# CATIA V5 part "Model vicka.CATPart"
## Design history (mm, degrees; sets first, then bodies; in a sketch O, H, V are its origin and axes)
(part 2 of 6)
  Sketch25 on zx-plane, origin (0, 0, 0), H (-1, 0, 0), V (0, 0, 1)
  Sketch26 on face of Pad13, origin (-3.8, 0, 0), H (0, -1, 0), V (0, 0, 1)
    projected line E1 (-60.7671, -19.7) -> (-56.1616, -20.7) from edge [face of Pad12 from Sketch20.L2 | face of Pad13]
    projected arc E2 centre (-32.0438, -10.8008) radius 26.0704 from (-57.6263, -15.8203) to (-56.1616, -20.7) ccw from edge [face of Pad12 | face of Pad13]
    projected arc E3 centre (-71.4411, -6.5318) radius 16.0003 from (-57.2443, -13.9114) to (-55.7471, -3.4163) ccw from edge [face of Pad12 | face of Pad13]
    projected arc E4 centre (-54.1383, -15.5258) radius 3.5004 from (-57.2443, -13.9114) to (-57.6263, -15.8203) ccw from edge [face of Pad12 | face of Pad13]
    projected arc E5 centre (-44.449, -1.1758) radius 11.5181 from (-55.9594, -0.7538) to (-55.7471, -3.4163) ccw from edge [face of Pad12 | face of Pad13]
    projected arc E6 centre (26.1964, -18.2876) radius 84.006 from (-32.7852, 41.5302) to (-55.9594, -0.7538) ccw from edge [face of Pad12 | face of Pad13]
    point P11 (-32.7852, 41.5302)
    projected arc E7 centre (-40.4358, 56.1497) radius 16.5003 from (-32.7852, 41.5302) to (-26.8741, 46.7508) ccw from edge [face of Pad12 from Sketch20.E38 | face of Pad13]
    projected arc E8 centre (-40.4358, 56.1497) radius 16.5003 from (-32.7852, 41.5302) to (-29.3749, 43.9056) ccw from edge [face of Pad12 from Sketch20.E38 | face of Pad13]
    point P13 (-32.7852, 41.5302)
    projected arc E9 centre (-40.437, 56.1511) radius 12.4808 from (-35.0969, 44.8704) to (-32.0107, 46.9441) ccw from edge [face of Rib1 | face of Chamfer2]
    projected arc E10 centre (-40.437, 56.1511) radius 12.4808 from (-35.0969, 44.8704) to (-32.3966, 46.6053) ccw from edge [face of Rib1 | face of Chamfer2]
    point P15 (-35.0969, 44.8704)
    projected line E11 (-35.1853, 44.8093) -> (-35.0969, 44.8704) from edge [face of Pad13 | face of Rib1]
    point P18 (-35.0969, 44.8704)
    projected arc E12 centre (26.197, -18.2879) radius 88.0287 from (-35.1853, 44.8093) to (-59.9554, -0.2097) ccw from edge [face of Rib1 | face of Pad13]
    projected line E13 (-59.963, -0.2667) -> (-59.9554, -0.2097) from edge [face of Pad13 | face of Rib1]
    projected arc E14 centre (-44.4489, -1.1757) radius 15.5408 from (-59.963, -0.2667) to (-59.7178, -4.0697) ccw from edge [face of Rib1 | face of Pad13]
    projected arc E15 centre (-71.4436, -6.5314) radius 11.9814 from (-60.7518, -11.9389) to (-59.7178, -4.0696) ccw from edge [face of Pad13 | face of Rib1]
    projected arc E16 centre (-54.1355, -15.5263) radius 7.5263 from (-60.7518, -11.9388) to (-61.5988, -16.4981) ccw from edge [face of Rib1 | face of Pad13]
    projected line E17 (-61.6023, -16.5212) -> (-61.5988, -16.4981) from edge [face of Pad13 | face of Rib1]
    point P29 (-61.6023, -16.5212)
    projected arc E18 centre (-32.0417, -10.7998) radius 30.1092 from (-61.6023, -16.5212) to (-59.1468, -23.9102) ccw from edge [face of Rib1 | face of Pad13]
    projected arc E19 centre (-32.0417, -10.7998) radius 30.1092 from (-61.6023, -16.5212) to (-60.8054, -19.7) ccw from edge [face of Rib1 | face of Pad13]
    point P31 (-61.6023, -16.5212)
    line L1 (-60.7671, -19.7) -> (-60.8054, -19.7)
    point P33 (-60.8054, -19.7)
    line L2 (-32.3966, 46.6053) -> (-29.3749, 43.9056)
    point P34 (-32.3966, 46.6053)
    point P35 (-29.3749, 43.9056)
    reference projected line E20 (-32.0107, 46.9441) -> (-33.0713, 47.7021) from edge [face of Fillet8 | face of Chamfer2]
    length L2 = 4.052
    distance P34 E20 = 0.5
    coincidence: P33 E18, P34 E9, P35 E7, P11 P13, P15 P18, P29 P31
    horizontal: L1 H
  Pad14: profile Sketch26, direction (-1, 0, 0), length 3.5
  Chamfer3: length 3.5, angle 27, on edge [face of Pad14 | end face of Pad14] (x6)
  Chamfer4: length 3.5, angle 46.25, on edge [face of Pad14 from Sketch26.L2 | end face of Pad14]
  Draft1: Angle 20, Neutral end face of Pad14, PullDir end face of Pad14, SupportToDraft face of Pad14, deactivated
  Draft2: Angle 19, Neutral end face of Pad14, PullDir end face of Pad14, SupportToDraft face of Pad14
  Chamfer5: length 0.044, angle 21, on edge [face of Pad14 | end face of Pocket8]
  Draft3: Angle 20, Neutral end face of Pad14, PullDir end face of Pad14, SupportToDraft face of Pad14, deactivated
  Chamfer6: length 3, second length 1.8, on edge [end face of Pocket8 | face of Pad14] (x6)
  Sketch27 on end face of Pocket8, origin (-0.8, 0, 0), H (0, -1, 0), V (0, 0, 1)
    projected arc E1 centre (26.1964, -18.2876) radius 82.206 from (-31.7063, 40.0656) to (-54.1649, -0.9706) ccw from edge [face of Chamfer6 | end face of Pocket8]
    projected arc E2 centre (26.1964, -18.2876) radius 82.206 from (-50.6914, 10.8) to (-54.1649, -0.9706) ccw from edge [face of Chamfer6 | end face of Pocket8]
    point P2 (-54.1649, -0.9706)
    projected arc E3 centre (-44.449, -1.1758) radius 9.7181 from (-54.1649, -0.9706) to (-53.9815, -3.0662) ccw from edge [face of Chamfer6 | end face of Pocket8]
    point P3 (-54.1649, -0.9706)
    projected arc E4 centre (-71.4411, -6.5318) radius 17.8003 from (-55.6471, -14.7416) to (-53.9815, -3.0658) ccw from edge [face of Chamfer6 | end face of Pocket8]
    projected arc E5 centre (-32.0438, -10.8008) radius 24.2704 from (-55.8377, -15.5862) to (-52.541, -23.7975) ccw from edge [face of Chamfer6 | end face of Pocket8]
    projected arc E6 centre (-54.1383, -15.5258) radius 1.7004 from (-55.6471, -14.7415) to (-55.8377, -15.5862) ccw from edge [face of Chamfer6 | end face of Pocket8]
    projected line E7 (-52.541, -23.7975) -> (-59.867, -22.2068) from edge [face of Chamfer5 | end face of Pocket8]
    projected arc E8 centre (-32.0451, -10.8014) radius 30.0689 from (-59.867, -22.2068) to (-55.0696, -30.1408) ccw from edge [face of Pad11 | end face of Pocket8]
    projected line E9 (-55.0696, -30.1408) -> (-41.0575, -46.8228) from edge [face of Pad11 | end face of Pocket8]
    projected arc E10 centre (-32.4622, -37.7466) radius 12.5004 from (-41.0575, -46.8228) to (-32.5168, -50.2468) ccw from edge [face of Pad11 | end face of Pocket8]
    projected line E11 (-32.5168, -50.2468) -> (-19.8409, -42.7) from edge [face of Pad11 | end face of Pocket8]
    projected line E12 (-21.7813, -39.2) -> (-19.8409, -42.7) from edge [end face of Pocket8 | face of Pad13 from Sketch21.L1]
    projected line E13 (-20.0483, -38.1682) -> (-21.7813, -39.2) from edge [end face of Pocket8 | face of Pad13 from Sketch21.E11]
    projected arc E14 centre (-12.1074, -51.5204) radius 15.5351 from (-14.1632, -36.1219) to (-20.0483, -38.1682) ccw from edge [end face of Pocket8 | face of Pad13 from Sketch21.E9]
    projected arc E15 centre (-12.1074, -51.5204) radius 15.5351 from (-15.7785, -36.4253) to (-20.0483, -38.1682) ccw from edge [end face of Pocket8 | face of Pad13 from Sketch21.E9]
    line L1 (-15.7785, -36.4253) -> (-15.7785, 10.8)
    line L2 (-15.7785, 10.8) -> (-50.6914, 10.8)
    reference projected arc E16 centre (-26.45, -66.45) radius 6.25 from (-32.7, -66.45) to (-20.2, -66.45) ccw from edge [face of Pad10 from Sketch17.A1 | end face of Pad10]
    reference projected arc E17 centre (-69.7785, -6.9628) radius 6 from (-73.6417, -2.372) to (-72.0998, -12.4956) ccw from edge [face of Pad10 from Sketch17.A4 | end face of Pad10]
    point P28 (-15.7785, -36.4253)
    point P29 (-15.7785, -36.4253)
    point P30 (-50.6914, 10.8)
    distance L2 E16 = 83.5
    distance L1 E17 = 60
    vertical: L1 V
    horizontal: L2 H
    coincidence: L1 P28, E14 P29, E1 P30, P2 P3, P28 P29
  Pocket9: profile Sketch27, direction (1, 0, 0), length 2
  Chamfer7: length 2, angle 25, on edge [face of Pocket9 from Sketch27.E7 | end face of Pocket9]
  Fillet10: radius 0.3, on edge [face of Chamfer5 | face of Pad14]
  Chamfer8: length 2, angle 25, on edge [face of Pocket9 from Sketch27.E5 | end face of Pocket9]
  Chamfer9: length 2, angle 25, on edge [face of Pocket9 from Sketch27.E2 | end face of Pocket9]
  Chamfer10: length 2, angle 25, on edge [face of Pocket9 from Sketch27.E4 | end face of Pocket9]
  Fillet11: radius 0.2, on edge [face of Rib1 | face of Pad13]
  Sketch28 on face of Pad13, origin (-3.8, 0, 0), H (0, -1, 0), V (0, 0, 1)
    line L1 (-9.148, 57.9141) -> (0.8348, 58.5004)
    line L2 (0.7586, 59.7982) -> (-9.2242, 59.2119)
    line L3 (-9.2242, 59.2119) -> (-9.148, 57.9141)
    reference projected arc E1 centre (-38.2049, 58.0324) radius 6 from (-35.5164, 63.3963) to (-44.0926, 56.8771) ccw from edge [face of Pad10 from Sketch17.A7 | end face of Pad10]
    reference projected line E2 (7.7671, 60.2098) -> (-13.9863, 58.9322) from edge [face of Pad11 from Sketch19.L17 | end face of Pad11]
    line L4 (0.8348, 58.5004) -> (0.7586, 59.7982)
    point P5 (0.7586, 59.7982)
    distance L3 E1 = 35
    distance L2 E2 = 0
    length L2 = 10
    length L1 = 10
    angle L4 L2 = 90
    length L4 = 1.3
    length L3 = 1.3
    perpendicularity: L3 L1
    coincidence: P5 L2
  Pad15: profile Sketch28, direction (-1, 0, 0), length 5
  Chamfer11: length 5, angle 35, on edge [face of Pad15 from Sketch28.L4 | end face of Pad15]
  Chamfer12: length 5, angle 35, on edge [face of Pad15 from Sketch28.L3 | end face of Pad15]
  Sketch29 on face of Pad13, origin (-3.8, 0, 0), H (0, -1, 0), V (0, 0, 1)
    projected line E1 (45.4892, -38.83) -> (48.9451, -41.08) from edge [face of Pad12 from Sketch20.L3 | face of Pad13]
    point P1 (45.4892, -38.83)
    point P2 (48.9451, -41.08)
    projected arc E2 centre (17.6227, -8.0775) radius 41.5001 from (45.4892, -38.83) to (58.5341, -15.0428) ccw from edge [face of Pad12 from Sketch20.E21 | face of Pad13]
    projected arc E3 centre (17.6227, -8.0775) radius 41.5001 from (45.4892, -38.83) to (51.8074, -31.6076) ccw from edge [face of Pad12 from Sketch20.E21 | face of Pad13]
    point P3 (45.4892, -38.83)
    offset arc E4 centre (17.6227, -8.0775) radius 45.5002 from (48.1751, -41.7942) to (62.4774, -15.7142) ccw from edge [face of Pad12 from Sketch20.E21 | face of Pad13]
    offset arc E5 centre (17.6227, -8.0775) radius 45.5002 from (48.9451, -41.08) to (55.1606, -33.7907) ccw from edge [face of Pad12 from Sketch20.E21 | face of Pad13]
    point P7 (48.9451, -41.08)
    line L1 (55.1606, -33.7907) -> (51.8074, -31.6076)
    point P8 (55.1606, -33.7907)
    point P9 (51.8074, -31.6076)
    distance E1 L1 = 9.5
    coincidence: E4 P7, P7 P2, P8 E4, P9 E2, P1 P3
  Pocket10: profile Sketch29, direction (1, 0, 0), length 1.6
  Chamfer13: length 1.6, angle 80, on edge [face of Pad13 | face of Pocket10 from Sketch29.L1]
  Fillet12: radius 0.5, on edge [face of Chamfer4 | end face of Pad14]
  Fillet13: radius 0.5, on edge [face of Chamfer3 | face of Chamfer3]; edge [face of Chamfer6 | face of Chamfer6]; edge [face of Chamfer3 | face of Chamfer6]; edge [face of Chamfer6 | end face of Pocket8]
  Sketch30 on face of Pad13, origin (-3.8, 0, 0), H (0, -1, 0), V (0, 0, 1)
    projected arc E1 centre (8.7519, 43.4398) radius 16.7989 from (22.3749, 53.2691) to (7.7671, 60.2098) ccw from edge [face of Pad11 from Sketch19.C13 | face of Pad13]
    projected arc E2 centre (8.7519, 43.4398) radius 16.7989 from (22.3749, 53.2691) to (22.1129, 53.6224) ccw from edge [face of Pad11 from Sketch19.C13 | face of Pad13]
    projected arc E3 centre (31.5753, 59.6553) radius 11.1993 from (22.3873, 53.2517) to (31.7756, 48.4578) ccw from edge [face of Pad11 from Sketch19.C14 | face of Pad13]
    projected arc E4 centre (31.8973, 41.6586) radius 6.8003 from (36.284, 46.8547) to (31.7756, 48.4578) ccw from edge [face of Pad11 from Sketch19.C15 | face of Pad13]
    projected arc E5 centre (2.5836, 1.1226) radius 56.8013 from (55.9532, 20.5668) to (36.4409, 46.7304) ccw from edge [face of Pad11 from Sketch19.C16 | face of Pad13]
    projected arc E6 centre (2.5836, 1.1226) radius 56.8013 from (50.4422, 31.7159) to (36.4409, 46.7304) ccw from edge [face of Pad11 from Sketch19.C16 | face of Pad13]
    point P8 (36.4409, 46.7304)
    offset arc E7 centre (8.7518, 43.4395) radius 15.4991 from (21.3206, 52.5086) to (7.8433, 58.912) ccw from edge [face of Pad11 from Sketch19.C13 | face of Pad13]
    offset arc E8 centre (8.7518, 43.4395) radius 15.4991 from (21.3206, 52.5086) to (21.0691, 52.8474) ccw from edge [face of Pad11 from Sketch19.C13 | face of Pad13]
    point P9 (21.3206, 52.5086)
    offset arc E9 centre (31.5754, 59.6555) radius 12.4995 from (21.3206, 52.5086) to (31.7989, 47.158) ccw from edge [face of Pad11 from Sketch19.C14 | face of Pad13]
    point P11 (21.3206, 52.5086)
    point P12 (31.7989, 47.158)
    point P13 (21.3206, 52.5086)
    offset arc E10 centre (31.8966, 41.6568) radius 5.502 from (35.4454, 45.8614) to (31.7989, 47.158) ccw from edge [face of Pad11 from Sketch19.C15 | face of Pad13]
    point P14 (35.4454, 45.8614)
    point P16 (31.7989, 47.158)
    offset arc E11 centre (2.5829, 1.1221) radius 55.5117 from (54.7407, 20.1251) to (35.6717, 45.6943) ccw from edge [face of Pad11 from Sketch19.C16 | face of Pad13]
    offset arc E12 centre (2.5829, 1.1221) radius 55.5117 from (49.389, 30.9672) to (35.6717, 45.6943) ccw from edge [face of Pad11 from Sketch19.C16 | face of Pad13]
    point P19 (35.4454, 45.8614)
    line L1 (22.1129, 53.6224) -> (21.0691, 52.8474)
    point P20 (22.1129, 53.6224)
    point P21 (21.0691, 52.8474)
    reference projected arc E13 centre (25.4433, 83.6382) radius 20 from (19.8826, 64.4268) to (33.2273, 65.2151) ccw from edge [face of Pad10 from Sketch17.A23 | end face of Pad10]
    line L2 (49.389, 30.9672) -> (50.4422, 31.7159)
    point P22 (49.389, 30.9672)
    point P23 (50.4422, 31.7159)
    reference projected arc E14 centre (72.4489, 33.5138) radius 15 from (58.8572, 27.1683) to (68.7354, 18.9807) ccw from edge [face of Pad10 from Sketch17.A25 | end face of Pad10]
    projected line E15 (36.3605, 46.7901) -> (36.284, 46.8547) from edge [face of Pad11 from Sketch19.L19 | face of Pad13]
    projected line E16 (36.4409, 46.7304) -> (36.3605, 46.7901) from edge [face of Pad11 from Sketch19.L20 | face of Pad13]
    point P26 (36.4409, 46.7304)
    offset line E17 (35.5219, 45.7968) -> (35.4454, 45.8614) from edge [face of Pad11 from Sketch19.L19 | face of Pad13]
    point P28 (35.5219, 45.7968)
    point P30 (35.4454, 45.8614)
    offset line E18 (35.6661, 45.6866) -> (35.5857, 45.7463) from edge [face of Pad11 from Sketch19.L20 | face of Pad13]
    point P33 (35.553, 45.7706)
    line L3 (35.6661, 45.6866) -> (35.6717, 45.6943)
    line L4 (35.5219, 45.7968) -> (35.5857, 45.7463)
    line L5 (22.3873, 53.2517) -> (22.3749, 53.2691)
    distance P21 E13 = 11.1
    distance P20 E13 = 10.2
    distance P22 E14 = 8.2
    distance P23 E14 = 7.08
    coincidence: E9 P13, P13 P9, E10 P16, P16 P12, E11 P19, P19 P14, P20 E1, P21 E7, P22 E11, P23 E5, E17 P30, P30 P14, E18 P33, P33 E17, E18 P28, P8 P26, P9 P11
    tangency: E10 E9, E17 E10
  Pad16: profile Sketch30, direction (-1, 0, 0), length 5
  Sketch31 on face of Pad13, origin (-3.8, 0, 0), H (0, -1, 0), V (0, 0, 1)
    projected arc E1 centre (2.5829, 1.1221) radius 55.5117 from (49.389, 30.9672) to (35.6717, 45.6943) ccw from edge [face of Pad16 from Sketch30.E12 | end face of Pad16]
    projected arc E2 centre (2.5829, 1.1221) radius 55.5117 from (44.2819, 37.7655) to (37.2055, 44.5136) ccw from edge [face of Pad16 from Sketch30.E12 | end face of Pad16]
    point P3 (44.2819, 37.7655)
    point P4 (41.129, 35.2788)
    reference projected line E3 (49.389, 30.9672) -> (50.4422, 31.7159) from edge [face of Pad16 from Sketch30.L2 | end face of Pad16]
    line L1 (37.2055, 44.5136) -> (34.6189, 41.4479)
    point P5 (37.2055, 44.5136)
    point P6 (34.6189, 41.4479)
    line L2 (44.2819, 37.7655) -> (41.129, 35.2788)
    arc A1 centre (2.5799, 1.1183) radius 51.507 from (41.129, 35.2788) to (34.6189, 41.4479) ccw
    point P8 (34.6189, 41.4479)
    reference projected curve E4 from edge [face of Pad12 | end face of Pad12]
    distance P4 E3 = 8.3
    distance P3 E3 = 8.5
    distance P5 E3 = 18.1
    distance P6 E3 = 17.1
    distance A1 E4 = 0
    distance P8 P6 = 0
    distance P6 E4 = 0
    distance P4 E4 = 0
    coincidence: P3 E1, P5 E1
  Pad17: profile Sketch31, direction (-1, 0, 0), length 4.3
  Chamfer14: length 5, angle 35, on edge [face of Pad16 from Sketch30.L1 | end face of Pad16]
  Chamfer15: length 5, angle 35, on edge [face of Pad16 from Sketch30.L2 | end face of Pad16]
  Chamfer16: length 4.3, angle 30, on edge [face of Pad17 from Sketch31.L1 | end face of Pad17]
  Sketch32 on face of Pad13, origin (-3.8, 0, 0), H (0, -1, 0), V (0, 0, 1)
    projected arc E1 centre (80.9167, 12.7937) radius 23.2008 from (57.7336, 13.7) to (61.5616, 0.0007) ccw from edge [face of Pad11 from Sketch19.C19 | face of Pad13]
    projected arc E2 centre (80.9167, 12.7937) radius 23.2008 from (58.6305, 6.3433) to (61.5616, 0.0007) ccw from edge [face of Pad11 from Sketch19.C19 | face of Pad13]
    point P2 (61.5616, 0.0007)
    projected arc E3 centre (37.3384, -11.4344) radius 26.8007 from (63.7589, -15.9323) to (61.6567, -0.1697) ccw from edge [face of Pad11 from Sketch19.C20 | face of Pad13]
    projected arc E4 centre (37.3384, -11.4344) radius 26.8007 from (62.2804, -1.6278) to (61.6567, -0.1697) ccw from edge [face of Pad11 from Sketch19.C20 | face of Pad13]
    point P4 (61.6567, -0.1697)
    offset arc E5 centre (37.335, -11.4349) radius 25.5039 from (62.4774, -15.7141) to (60.4771, -0.7161) ccw from edge [face of Pad11 from Sketch19.C20 | face of Pad13]
    offset arc E6 centre (37.335, -11.4349) radius 25.5039 from (61.1107, -2.2063) to (60.4771, -0.7161) ccw from edge [face of Pad11 from Sketch19.C20 | face of Pad13]
    point P6 (60.4771, -0.7161)
    offset arc E7 centre (80.9204, 12.7948) radius 24.5046 from (56.4345, 13.7508) to (60.4771, -0.7161) ccw from edge [face of Pad11 from Sketch19.C19 | face of Pad13]
    offset arc E8 centre (80.9204, 12.7948) radius 24.5046 from (57.3926, 5.9452) to (60.4771, -0.7161) ccw from edge [face of Pad11 from Sketch19.C19 | face of Pad13]
    point P8 (60.4771, -0.7161)
    point P9 (60.4771, -0.7161)
    projected line E9 (61.6567, -0.1697) -> (61.6156, -0.0809) from edge [face of Pad11 from Sketch19.L24 | face of Pad13]
    point P10 (61.6567, -0.1697)
    projected line E10 (61.6156, -0.0809) -> (61.5616, 0.0007) from edge [face of Pad11 from Sketch19.L23 | face of Pad13]
    point P13 (61.5616, 0.0007)
    line L1 (62.2804, -1.6278) -> (61.1107, -2.2063)
    point P14 (62.2804, -1.6278)
    point P15 (61.1107, -2.2063)
    line L2 (58.6305, 6.3433) -> (57.3926, 5.9452)
    point P16 (58.6305, 6.3433)
    point P17 (57.3926, 5.9452)
    reference projected arc E11 centre (68.2522, 13.0002) radius 6 from (72.7846, 9.0686) to (68.7354, 18.9807) ccw from edge [face of Pad10 from Sketch17.A12 | end face of Pad10]
    distance P15 E11 = 10.8
    distance P14 E11 = 9.8
    distance P17 E11 = 6.95
    distance P16 E11 = 17.7
    coincidence: E7 P9, P9 P6, P14 E3, P15 E5, P16 E1, P17 E7, P2 P13, P4 P10, P6 P8
  Pad18: profile Sketch32, direction (-1, 0, 0), length 5
  Sketch33 on face of Pad13, origin (-3.8, 0, 0), H (0, -1, 0), V (0, 0, 1)
    projected line E1 (-32.1617, -51.5484) -> (-17.337, -42.7222) from edge [face of Pad11 from Sketch19.L4 | face of Pad13]
    projected line E2 (-19.1759, -43.817) -> (-17.337, -42.7222) from edge [face of Pad11 from Sketch19.L4 | face of Pad13]
    point P2 (-17.337, -42.7222)
    projected arc E3 centre (-12.1075, -51.5201) radius 10.2348 from (-13.3693, -41.3634) to (-17.337, -42.7222) ccw from edge [face of Pad11 from Sketch19.C4 | face of Pad13]
    point P4 (-17.337, -42.7222)
    projected arc E4 centre (1.1744, -116.1677) radius 76.2019 from (16.6339, -41.5504) to (-13.282, -41.3496) ccw from edge [face of Pad11 from Sketch19.C3 | face of Pad13]
    projected arc E5 centre (1.1744, -116.1677) radius 76.2019 from (-5.8345, -40.2888) to (-13.282, -41.3496) ccw from edge [face of Pad11 from Sketch19.C3 | face of Pad13]
    offset arc E6 centre (-12.1074, -51.5204) radius 11.5351 from (-13.5286, -40.0732) to (-18.002, -41.6052) ccw from edge [face of Pad11 from Sketch19.C4 | face of Pad13]
    point P7 (-13.5286, -40.0732)
    offset arc E7 centre (1.1744, -116.1695) radius 77.5037 from (16.8977, -40.2774) to (-13.5286, -40.0732) ccw from edge [face of Pad11 from Sketch19.C3 | face of Pad13]
    offset arc E8 centre (1.1744, -116.1695) radius 77.5037 from (-6.0276, -39.0011) to (-13.5286, -40.0732) ccw from edge [face of Pad11 from Sketch19.C3 | face of Pad13]
    point P10 (-13.5286, -40.0732)
    point P11 (-13.5286, -40.0732)
    offset line E9 (-32.8268, -50.4314) -> (-18.002, -41.6052) from edge [face of Pad11 from Sketch19.L4 | face of Pad13]
    offset line E10 (-19.8409, -42.7) -> (-18.002, -41.6052) from edge [face of Pad11 from Sketch19.L4 | face of Pad13]
    line L1 (-19.8409, -42.7) -> (-19.1759, -43.817)
    point P14 (-19.8409, -42.7)
    point P15 (-19.1759, -43.817)
    line L2 (-6.0276, -39.0011) -> (-5.8345, -40.2888)
    point P16 (-6.0276, -39.0011)
    point P17 (-5.8345, -40.2888)
    reference projected line E11 (-21.7813, -39.2) -> (-19.8409, -42.7) from edge [face of Pocket9 | face of Pad13]
    line L3 (-13.3693, -41.3634) -> (-13.282, -41.3496)
    distance P14 E11 = 0
    distance P15 P17 = 13.8
    distance P16 P14 = 14.3
    coincidence: E7 P11, P11 P7, P14 E9, P15 E1, P16 E7, P17 E4, P4 P2, P7 P10
    tangency: E9 E6
    perpendicularity: L1 E1
  Pad19: profile Sketch33, direction (-1, 0, 0), length 5
  Sketch34 on face of Pad13, origin (-3.8, 0, 0), H (0, -1, 0), V (0, 0, 1)
    projected line E1 (-21.7813, -39.2) -> (-19.8409, -42.7) from edge [face of Pocket9 | face of Pad13]
    projected arc E2 centre (-12.1074, -51.5204) radius 15.5351 from (-14.1632, -36.1219) to (-20.0483, -38.1682) ccw from edge [face of Pocket9 | face of Pad13]
    point P3 (-14.1632, -36.1219)
    projected line E3 (-20.0483, -38.1682) -> (-21.7813, -39.2) from edge [face of Pocket9 | face of Pad13]
    projected arc E4 centre (1.1744, -116.1678) radius 81.5021 from (17.7092, -36.3606) to (-14.1632, -36.1219) ccw from edge [face of Pad13 from Sketch21.E7 | face of Pad13]
    projected arc E5 centre (1.1744, -116.1678) radius 81.5021 from (-7.0441, -35.0812) to (-14.1632, -36.1219) ccw from edge [face of Pad13 from Sketch21.E7 | face of Pad13]
    point P8 (-14.1632, -36.1219)
    projected line E6 (-18.002, -41.6052) -> (-19.8409, -42.7) from edge [face of Pad13 | face of Pad19 from Sketch33.E10]
    projected arc E7 centre (-12.1074, -51.5204) radius 11.5351 from (-13.5286, -40.0732) to (-18.002, -41.6052) ccw from edge [face of Pad13 | face of Pad19 from Sketch33.E6]
    projected arc E8 centre (1.1744, -116.1695) radius 77.5037 from (-6.0276, -39.0011) to (-13.5286, -40.0732) ccw from edge [face of Pad13 | face of Pad19 from Sketch33.E8]
    line L1 (-6.0276, -39.0011) -> (-7.0441, -35.0812)
    point P15 (-7.0441, -35.0812)
    coincidence: P15 E6, P15 E4, P3 P8
  Pad20: profile Sketch34, direction (-1, 0, 0), length 4.3
  Sketch35 on face of Pad13, origin (-3.8, 0, 0), H (0, -1, 0), V (0, 0, 1)
    projected arc E1 centre (32.0711, -43.2237) radius 8.8 from (24.279, -47.313) to (35.4262, -51.359) ccw from edge [face of Pad11 from Sketch19.C1 | face of Pad13]
    projected arc E2 centre (32.0711, -43.2237) radius 8.8 from (24.279, -47.313) to (25.054, -48.534) ccw from edge [face of Pad11 from Sketch19.C1 | face of Pad13]
    point P1 (24.279, -47.313)
    projected arc E3 centre (14.3612, -52.5182) radius 11.2008 from (24.279, -47.313) to (16.6339, -41.5504) ccw from edge [face of Pad11 from Sketch19.C2 | face of Pad13]
    point P3 (24.279, -47.313)
    point P4 (16.6339, -41.5504)
    projected arc E4 centre (1.1744, -116.1681) radius 76.2023 from (16.6339, -41.5504) to (-5.8345, -40.2888) ccw from edge [face of Pad11 from Sketch19.C3 | face of Pad13]
    projected arc E5 centre (1.1744, -116.1681) radius 76.2024 from (16.6339, -41.5504) to (5.7125, -40.101) ccw from edge [face of Pad11 from Sketch19.C3 | face of Pad13]
    point P5 (16.6339, -41.5504)
    offset arc E6 centre (32.0712, -43.2236) radius 7.5 from (25.4301, -46.7089) to (34.9305, -50.1572) ccw from edge [face of Pad11 from Sketch19.C1 | face of Pad13]
    offset arc E7 centre (32.0712, -43.2236) radius 7.5 from (25.4301, -46.7089) to (25.9543, -47.5636) ccw from edge [face of Pad11 from Sketch19.C1 | face of Pad13]
    point P7 (25.4301, -46.7089)
    offset arc E8 centre (14.361, -52.5184) radius 12.501 from (25.4301, -46.7089) to (16.8977, -40.2774) ccw from edge [face of Pad11 from Sketch19.C2 | face of Pad13]
    point P9 (25.4301, -46.7089)
    point P10 (16.8977, -40.2774)
    point P11 (25.4301, -46.709)
    offset arc E9 centre (1.1744, -116.1686) radius 77.5029 from (16.8977, -40.2774) to (-5.9541, -38.9943) ccw from edge [face of Pad11 from Sketch19.C3 | face of Pad13]
    offset arc E10 centre (1.1744, -116.1686) radius 77.5029 from (16.8977, -40.2774) to (5.7706, -38.8022) ccw from edge [face of Pad11 from Sketch19.C3 | face of Pad13]
    point P12 (16.8977, -40.2774)
    point P14 (16.8977, -40.2774)
    line L1 (25.9543, -47.5636) -> (25.054, -48.534)
    point P15 (25.9543, -47.5636)
    point P16 (25.054, -48.534)
    line L2 (5.7706, -38.8022) -> (5.7125, -40.101)
    point P17 (5.7706, -38.8022)
    point P18 (5.7125, -40.101)
    reference projected line E11 (25.8877, -47.68) -> (28.2315, -43.58) from edge [face of Pad13 from Sketch21.L2 | face of Pad13]
    distance P15 E11 = 0
    distance P16 E11 = 0.3
    distance P17 P16 = 21.6
    distance P18 P16 = 21.1
    tangency: E8 E6, E9 E8
    coincidence: E8 P11, P11 E6, E9 P14, P14 P10, P15 E6, P16 E1, P17 E9, P18 E4, P1 P3, P4 P5, P7 P9, P10 P12
  Pad21: profile Sketch35, direction (-1, 0, 0), length 5
  Chamfer17: length 5, angle 35, on edge [face of Pad21 from Sketch35.L1 | end face of Pad21]; edge [face of Pad21 from Sketch35.L2 | end face of Pad21]
  Chamfer18: length 7.3, angle 10, on edge [face of Pad20 | end face of Pad20] (x2)
  Chamfer19: length 4.3, angle 20, on edge [face of Pad20 from Sketch34.L1 | end face of Pad20]
  Chamfer20: length 3, angle 10, on edge [face of Pad13 from Sketch21.A1 | face of Pad13]
  Sketch36 on face of Pad20, origin (0, 33.2837, -18.4526), H (-1, 0, 0), V (0, 0.4849, 0.8746)
    projected line E1 (-1.2, -23.7226) -> (0.8, -23.7226) from edge [face of Pad20 | face of Pad20]
    line L1 (-1.2, -23.7226) -> (-1.2, -23.3338)
    line L2 (0.8, -23.7226) -> (-1.2, -23.3338)
    reference intersected line E2 (-1.2, -27.7245) -> (-1.2, 33.4474) from end face of Pocket9
    angle E2 L2 = 101
    vertical: L1 V
  Sketch37 on end face of Pocket9, origin (1.2, 0, 0), H (0, -1, 0), V (0, 0, 1)
    projected line E1 (-20.0483, -38.1682) -> (-21.7813, -39.2) from edge [face of Pad20 | face of Chamfer18]
    projected arc E2 centre (-12.1074, -51.5204) radius 15.5351 from (-15.7785, -36.4253) to (-20.0483, -38.1682) ccw from edge [face of Pad20 | face of Chamfer18]
  Rib2: profile Sketch36, centre curve Sketch37
  Plane1: type Tangent, Support face of Pad19 from Sketch33.E10, RefPoint vertex [face of Pad19 from Sketch33.L1 | end face of Pad19 | face of Pad19 from Sketch33.E10]
  Sketch38 on Plane1, origin (0, -13.5768, -22.8041), H (1, 0, 0), V (0, -0.8592, 0.5116)
    point P2 (1.2, -38.7569)
    line L1 (-8.1, -38.8085) -> (-8.1, -37.2041)
    line L2 (-8.1, -37.2041) -> (1.2, -38.7569)
    reference projected point E1 (-88.9039, -36.7593) from edge
    line L3 (1.2, -38.7569) -> (1.2, -39.8869)
    point P4 (1.2, -38.7569)
    point P5 (1.2, -39.8869)
    line L4 (1.2, -39.8869) -> (-8.1, -39.8869)
    point P6 (-8.1, -39.8869)
    line L5 (-8.1, -39.8869) -> (-8.1, -38.8085)
    reference intersected line E2 (-3.8, -61.5724) -> (-3.8, 70.6052) from end face of Pad10
    reference projected line E3 (1.2, -38.8921) -> (1.2, -53.6444) from edge [face of Pocket9 | end face of Pocket9]
    distance L2 E1 = 12.8691
    length L4 = 9.3
    length L5 = 1.0784
    length L1 = 1.6045
    angle L2 E2 = 99.4794
    distance P2 P5 = 1.13
    distance L3 E3 = 0
    vertical: L1 V, L3 V, L5 V
    coincidence: P4 L2, P6 L1
    horizontal: L4 H
  Pocket11: profile Sketch38, direction (0, 0.5116, 0.8592), length 5
  Chamfer21: length 5, angle 13, on edge [face of Pad19 from Sketch33.L1 | end face of Pad19]
  Chamfer22: length 5, angle 20, on edge [face of Pad19 from Sketch33.L2 | end face of Pad19]
  Fillet14: radius 0.5, on edge [face of Fillet13 | face of Pad13]; edge [face of Pad12 from Sketch20.E36 | face of Pad13]; edge [face of Pad12 from Sketch20.E34 | face of Pad13]; edge [face of Pad12 from Sketch20.A1 | face of Pad13]; edge [face of Pad12 from Sketch20.E32 | face of Pad13]; edge [face of Pad12 | face of Pad13]; edge [face of Pad12 from Sketch20.L1 | face of Pad13], deactivated
  Fillet15: radius 0.5, on edge [face of Fillet13 | face of Pad13]; edge [face of Pad12 from Sketch20.E36 | face of Pad13]; edge [face of Pad12 from Sketch20.E34 | face of Pad13]; edge [face of Pad12 from Sketch20.A1 | face of Pad13]; edge [face of Pad12 from Sketch20.E32 | face of Pad13]; edge [face of Pad12 | face of Pad13] (x2); edge [face of Pad12 from Sketch20.L1 | face of Pad13]
  Chamfer23: length 4.6, angle 20, on edge [face of Pad17 from Sketch31.L2 | end face of Pad17], deactivated
  Chamfer24: length 4.3, angle 30, on edge [face of Pad17 from Sketch31.L2 | end face of Pad17]
  Sketch39 on face of Pad13, origin (-3.8, 0, 0), H (0, -1, 0), V (0, 0, 1)
    line L1 (-18.2859, 52.0806) -> (-17.9906, 54.4623)
    point P1 (-18.2859, 52.0806)
    reference projected arc E1 centre (-7.4339, 25.3633) radius 28.9024 from (-13.3045, 53.6631) to (-26.0505, 47.4714) ccw from edge [face of Pad12 from Sketch20.E36 | face of Fillet15]
    line L2 (-17.9906, 54.4623) -> (-16.6508, 54.2962)
    line L3 (-16.6508, 54.2962) -> (-16.9462, 51.9145)
    line L4 (-16.9462, 51.9145) -> (-15.0312, 50.4678)
    point P5 (-15.0312, 50.4678)
    line L5 (-15.0312, 50.4678) -> (-15.8449, 49.3906)
    point P6 (-15.0312, 50.4678)
    line L6 (-15.8449, 49.3906) -> (-17.7599, 50.8373)
    line L7 (-17.7599, 50.8373) -> (-19.9702, 49.9022)
    line L8 (-19.9702, 49.9022) -> (-20.4962, 51.1455)
    point P10 (-20.4962, 51.1455)
    line L9 (-20.4962, 51.1455) -> (-18.2859, 52.0806)
    reference projected arc E2 centre (-38.2049, 58.0324) radius 6 from (-35.5164, 63.3963) to (-44.0926, 56.8771) ccw from edge [face of Pad10 from Sketch17.A7 | end face of Pad10]
    length L1 = 2.4
    distance P1 E1 = 0.0652
    length L2 = 1.35
    length L3 = 2.4
    angle L4 L3 = 120
    length L4 = 2.4
    length L5 = 1.35
    length L6 = 2.4
    distance P6 P5 = 0
    angle L7 L6 = 120
    length L7 = 2.4
    distance P10 E1 = 0
    distance L1 E2 = 26.5
    perpendicularity: L2 L1, L5 L4, L8 L7
    parallelism: L3 L1, L6 L4, L9 L7
    coincidence: P6 L4
  Pad22: profile Sketch39, direction (-1, 0, 0), length 7.25
  Pad23: profile Sketch39, direction (1, 0, 0), up to the existing solid (limit type 2)
  Fillet16: radius 0.5, on edge [face of Pad12 | face of Pad13]; edge [face of Pad12 from Sketch20.E29 | face of Pad13]; edge [face of Pad12 from Sketch20.E27 | face of Pad13]; edge [face of Pad12 from Sketch20.E25 | face of Pad13]; edge [face of Pad12 from Sketch20.E23 | face of Pad13]; edge [face of Pad12 from Sketch20.E21 | face of Chamfer13]; edge [face of Pad12 from Sketch20.E21 | end face of Pocket10]
  Sketch40 on face of Pad13, origin (-3.8, 0, 0), H (0, -1, 0), V (0, 0, 1)
    line L1 (57.4805, -21.9675) -> (58.9548, -23.166)
    point P1 (57.4805, -21.9675)
    point P2 (58.9548, -23.166)
    reference projected line E1 (59.527, -25.8057) -> (56.1164, -23.5853) from edge [face of Pad13 | face of Chamfer13]
    reference projected arc E2 centre (17.6227, -8.0775) radius 42.0001 from (56.5434, -23.8632) to (59.027, -15.1267) ccw from edge [face of Fillet16 | face of Pad13]
    line L2 (58.9548, -23.166) -> (58.1033, -24.2136)
    line L3 (58.1033, -24.2136) -> (56.629, -23.0151)
    line L4 (56.629, -23.0151) -> (55.4305, -24.4894)
    line L5 (55.4305, -24.4894) -> (54.3829, -23.6378)
    line L6 (54.3829, -23.6378) -> (55.5814, -22.1635)
    point P7 (55.5814, -22.1635)
    line L7 (55.5814, -22.1635) -> (54.1071, -20.965)
    point P8 (55.5814, -22.1635)
    line L8 (54.1071, -20.965) -> (54.9587, -19.9174)
    point P10 (54.9587, -19.9174)
    line L9 (54.9587, -19.9174) -> (56.433, -21.1159)
    point P11 (56.433, -21.1159)
    line L10 (56.433, -21.1159) -> (57.6315, -19.6416)
    point P12 (57.6315, -19.6416)
    line L11 (57.6315, -19.6416) -> (58.679, -20.4932)
    point P13 (57.6315, -19.6416)
    point P14 (58.679, -20.4932)
    line L12 (58.679, -20.4932) -> (57.4805, -21.9675)
    distance P1 E1 = 2.1
    length L1 = 1.9
    distance P2 E1 = 1.9
    distance P2 E2 = 2
    length L2 = 1.35
    length L4 = 1.9
    length L5 = 1.35
    length L7 = 1.9
    length L10 = 1.9
    distance P13 P12 = 0
    distance P8 P7 = 0
    perpendicularity: L2 L1, L12 L1
    parallelism: L3 L1, L4 L2, L5 L3, L6 L4, L7 L3, L8 L6, L9 L1, L10 L6, L11 L9
    coincidence: P7 L3, P8 L6, P10 L1, P11 L6, P13 L10, P14 L4
  Pad24: profile Sketch40, direction (-1, 0, 0), length 8.7
  Pad25: profile Sketch40, direction (1, 0, 0), length 3.2
  Sketch41 on end face of Pocket8, origin (-0.8, 0, 0), H (0, -1, 0), V (0, 0, 1)
    point P1 (-11.7785, -21.4253)
    line L1 (-11.7785, -21.4253) -> (-11.7785, -2.4253)
    point P2 (-11.7785, -2.4253)
    line L2 (-11.7785, -2.4253) -> (-3.8785, -2.4253)
    point P3 (-3.8785, -2.4253)
    line L3 (-3.8785, -2.4253) -> (-3.8785, 4.8747)
    point P4 (-3.8785, 4.8747)
    line L4 (-3.8785, 4.8747) -> (24.1215, 4.8747)
    point P5 (24.1215, 4.8747)
    line L5 (24.1215, 4.8747) -> (24.1215, -2.4253)
    point P6 (24.1215, -2.4253)
    line L6 (24.1215, -2.4253) -> (32.0215, -2.4253)
    point P7 (32.0215, -2.4253)
    line L7 (32.0215, -2.4253) -> (32.0215, -21.4253)
    point P8 (32.0215, -21.4253)
    line L8 (32.0215, -21.4253) -> (-11.7785, -21.4253)
    reference projected line E1 (-15.7785, -36.4253) -> (-15.7785, 10.8) from edge [end face of Pocket8 | face of Pocket9 from Sketch27.L1]
    reference projected point E2 (-15.7785, -36.4253) from vertex [face of Rib2 | face of Pocket9 from Sketch27.L1 | face of Rib2 | face of Chamfer18 | end face of Pocket8]
    construction line L9 (-8.6465, 7.1247) -> (33.608, 7.1247)
    point P11 (-11.7785, 35.6747)
    point P12 (32.0215, 35.6747)
    line L10 (32.0215, 35.6747) -> (-11.7785, 35.6747)
    point P13 (32.0215, 35.6747)
    point P14 (32.0215, 16.6747)
    line L11 (32.0215, 16.6747) -> (32.0215, 35.6747)
    point P15 (32.0215, 16.6747)
    point P16 (24.1215, 16.6747)
    line L12 (24.1215, 16.6747) -> (32.0215, 16.6747)
    point P17 (24.1215, 16.6747)
    point P18 (24.1215, 9.3747)
    line L13 (24.1215, 9.3747) -> (24.1215, 16.6747)
    point P19 (24.1215, 9.3747)
    point P20 (-3.8785, 9.3747)
    line L14 (-3.8785, 9.3747) -> (24.1215, 9.3747)
    point P21 (-3.8785, 9.3747)
    point P22 (-3.8785, 16.6747)
    line L15 (-3.8785, 16.6747) -> (-3.8785, 9.3747)
    point P23 (-3.8785, 16.6747)
    point P24 (-11.7785, 16.6747)
    line L16 (-11.7785, 16.6747) -> (-3.8785, 16.6747)
    point P25 (-11.7785, 16.6747)
    point P26 (-11.7785, 35.6747)
    line L17 (-11.7785, 35.6747) -> (-11.7785, 16.6747)
    distance L1 E1 = 4
    length L8 = 43.8
    distance L4 L8 = 26.3
    distance L8 E2 = 15
    distance L2 L8 = 19
    distance L3 L1 = 7.9
    length L4 = 28
    distance L9 L4 = 2.25
    vertical: L1 V, L3 V, L5 V, L7 V
    horizontal: L2 H, L4 H, L6 H, L8 H, L9 H
    coincidence: P6 L2, P11 P26, P12 P13, P14 P15, P16 P17, P18 P19, P20 P21, P22 P23, P24 P25
    symmetry: P1 P11 L9, P8 P12 L9, L8 L10 L9, P8 P13 L9, P7 P14 L9, L7 L11 L9, P7 P15 L9, P6 P16 L9, L6 L12 L9, P6 P17 L9, P5 P18 L9, L5 L13 L9, P5 P19 L9, P4 P20 L9, L4 L14 L9, P4 P21 L9, P3 P22 L9, L3 L15 L9, P3 P23 L9, P2 P24 L9, L2 L16 L9, P2 P25 L9, P1 P26 L9, L1 L17 L9
  Pad26: profile Sketch41, direction (-1, 0, 0), length 4.3
  Sketch42 on face of Pad9, origin (1.6, 0, 0), H (0, 1, 0), V (0, 0, 1)
  Pocket12: profile Sketch42, direction (-1, 0, 0), length 4.5
  Fillet17: radius 1.5, on end face of Pad26 (x2); edge [face of Pocket12 | end face of Pocket12] (x10)
  Sketch43 on face of Pocket12, origin (0, -23.1215, 0), H (-1, 0, 0), V (0, 0, 1)
    line L1 (-1.6, 3.8747) -> (-0.6, 3.8747)
    line L2 (-0.6, 3.8747) -> (-0.6, 0.3747)
    line L3 (-0.6, 0.3747) -> (-1.6, 0.3747)
    line L4 (-1.6, 0.3747) -> (-1.6, 3.8747)
    reference projected line E1 (-1.6, 3.8747) -> (-1.6, -3.4253) from edge [face of Pad9 | face of Pocket12]
    reference projected line E2 (-1.6, 3.8747) -> (2.9, 3.8747) from edge [face of Pocket12 | face of Pocket12]
    reference projected line E3 (2.9, -3.4253) -> (-1.6, -3.4253) from edge [face of Pocket12 | face of Pocket12]
    distance L4 E1 = 0
    distance L1 E2 = 0
    distance L3 E3 = 3.8
    length L3 = 1
    horizontal: L1 H, L3 H
    vertical: L2 V, L4 V
  Pad27: profile Sketch43, direction (0, 1, 0), up to the existing solid (limit type 2)
  Plane2: type Between, Element1 face of Pocket12, Element2 face of Pocket12, Ratio 0.5
  Mirror1: of Pad27, about Plane2
  Fillet18: radius 1.5, on edge [face of Pad27 from Sketch43.L2 | face of Pad27 from Sketch43.L3]; edge [face of Mirror1 | face of Mirror1]
  Sketch44 on end face of Pad10, origin (-3.8, 0, 0), H (0, -1, 0), V (0, 0, 1)
    point P1 (26.2, -66.08)
    point P2 (-26.45, -66.45)
    point P3 (-70.2785, -7.2128)
    point P4 (-38.2049, 58.0324)
    point P5 (35.5625, 59.6882)
    point P6 (68.2522, 13.0002)
    reference projected arc E1 centre (26.2, -66.08) radius 6 from (20.2, -66.08) to (31.7249, -63.7401) ccw from edge [face of Pad10 from Sketch17.A17 | end face of Pad10]
    reference projected arc E2 centre (-26.45, -66.45) radius 6.25 from (-32.7, -66.45) to (-20.2, -66.45) ccw from edge [face of Pad10 from Sketch17.A1 | end face of Pad10]
    reference projected arc E3 centre (-38.2049, 58.0324) radius 6 from (-35.5164, 63.3963) to (-44.0926, 56.8771) ccw from edge [face of Pad10 from Sketch17.A7 | end face of Pad10]
    reference projected arc E4 centre (35.5625, 59.6882) radius 6 from (41.2484, 57.7725) to (33.2273, 65.2151) ccw from edge [face of Pad10 from Sketch17.A11 | end face of Pad10]
    reference projected arc E5 centre (68.2522, 13.0002) radius 6 from (72.7846, 9.0686) to (68.7354, 18.9807) ccw from edge [face of Pad10 from Sketch17.A12 | end face of Pad10]
    reference projected arc E6 centre (-69.7785, -6.9628) radius 6 from (-73.6417, -2.372) to (-72.0998, -12.4956) ccw from edge [face of Pad10 from Sketch17.A4 | end face of Pad10]
    distance P3 E6 H = 5.5
    distance P3 E6 V = 6.25
    concentricity: E1 P1, E2 P2, E3 P4, E4 P5, E5 P6
  Sketch45 on end face of Pad10, origin (-3.8, 26.45, -66.45), H (0, 1, 0), V (0, 0, -1)
    point P1 (0, 0)
    reference projected point E1 (0, 0) from Sketch44.P2
    coincidence: E1 P1
  Hole1: placed by Sketch45, at (-3.8, 26.45, -66.45) direction (1, 0, 0), diameter 6, through (limit type 6), counterbore diameter 10, counterbore depth 2
  Sketch46 on end face of Pad10, origin (-3.8, 70.2785, -7.2128), H (0, 1, 0), V (0, 0, -1)
    point P1 (0, 0)
    reference projected point E1 (0, 0) from Sketch44.P3
    coincidence: E1 P1
  Hole2: placed by Sketch46, at (-3.8, 70.2785, -7.2128) direction (1, 0, 0), diameter 6, through (limit type 6), counterbore diameter 10, counterbore depth 2
  Sketch47 on end face of Pad10, origin (-3.8, 38.2049, 58.0324), H (0, 1, 0), V (0, 0, -1)
    point P1 (0, 0)
    reference projected point E1 (0, 0) from Sketch44.P4
    coincidence: E1 P1
  Hole3: placed by Sketch47, at (-3.8, 38.2049, 58.0324) direction (1, 0, 0), diameter 6, through (limit type 6), counterbore diameter 10, counterbore depth 2
  Sketch48 on end face of Pad10, origin (-3.8, -35.6864, 59.6426), H (0, 1, 0), V (0, 0, -1)
    point P1 (0, 0)
  Hole4: placed by Sketch48, at (-3.8, -35.6864, 59.6426) direction (1, 0, 0), diameter 6, through (limit type 6), counterbore diameter 10, counterbore depth 2
  Sketch49 on end face of Pad10, origin (-3.8, -68.2522, 13.0002), H (0, 1, 0), V (0, 0, -1)
    point P1 (0, 0)
    reference projected point E1 (0, 0) from Sketch44.P6
    coincidence: E1 P1
  Hole5: placed by Sketch49, at (-3.8, -68.2522, 13.0002) direction (1, 0, 0), diameter 6, through (limit type 6), counterbore diameter 10, counterbore depth 2
  Sketch50 on end face of Pad10, origin (-3.8, -26.2, -66.08), H (0, 1, 0), V (0, 0, -1)
    point P1 (0, 0)
    reference projected point E1 (0, 0) from Sketch44.P1
    coincidence: E1 P1
  Hole6: placed by Sketch50, at (-3.8, -26.2, -66.08) direction (1, 0, 0), diameter 6, through (limit type 6), counterbore diameter 10, counterbore depth 2
  Sketch51 on face of Pad9, origin (1.6, 38.2049, 58.0324), H (0, 1, 0), V (0, 0, 1)
    point P1 (0, 0)
    reference projected point E1 (0, 0) from Sketch44.P4
    coincidence: E1 P1
  Hole7: placed by Sketch51, at (1.6, 38.2049, 58.0324) direction (-1, 0, 0), diameter 6, through (limit type 6), counterbore diameter 10, counterbore depth 2
  Sketch52 on face of Pad9, origin (1.6, -35.5625, 59.6882), H (0, 1, 0), V (0, 0, 1)
    point P1 (0, 0)
    reference projected point E1 (0, 0) from Sketch44.P5
    coincidence: E1 P1
  Hole8: placed by Sketch52, at (1.6, -35.5625, 59.6882) direction (-1, 0, 0), diameter 6, through (limit type 6), counterbore diameter 10, counterbore depth 2
  Sketch53 on face of Pad9, origin (1.6, -68.2522, 13.0002), H (0, 1, 0), V (0, 0, 1)
    point P1 (0, 0)
    reference projected point E1 (0, 0) from Sketch44.P6
    coincidence: E1 P1
  Hole9: placed by Sketch53, at (1.6, -68.2522, 13.0002) direction (-1, 0, 0), diameter 6, through (limit type 6), counterbore diameter 10, counterbore depth 2
  Sketch54 on face of Pad9, origin (1.6, -26.2, -66.08), H (0, 1, 0), V (0, 0, 1)
    point P1 (0, 0)
    reference projected point E1 (0, 0) from Sketch44.P1
    coincidence: E1 P1
  Hole10: placed by Sketch54, at (1.6, -26.2, -66.08) direction (-1, 0, 0), diameter 6, through (limit type 6), counterbore diameter 10, counterbore depth 2
  Sketch55 on face of Pad9, origin (1.6, 26.45, -66.45), H (0, 1, 0), V (0, 0, 1)
    point P1 (0, 0)
    reference projected point E1 (0, 0) from Sketch44.P2
    coincidence: E1 P1
  Hole11: placed by Sketch55, at (1.6, 26.45, -66.45) direction (-1, 0, 0), diameter 6, through (limit type 6), counterbore diameter 10, counterbore depth 2
  Sketch56 on face of Pad9, origin (1.6, 70.2785, -7.2128), H (0, 1, 0), V (0, 0, 1)
    point P1 (0, 0)
    reference projected point E1 (0, 0) from Sketch44.P3
    coincidence: E1 P1
  Hole12: placed by Sketch56, at (1.6, 70.2785, -7.2128) direction (-1, 0, 0), diameter 6, through (limit type 6), counterbore diameter 10, counterbore depth 2
  Fillet19: radius 1.5, on edge [face of Pad26 from Sketch41.L11 | face of Pad26 from Sketch41.L12]; edge [face of Pad26 from Sketch41.L10 | face of Pad26 from Sketch41.L11]; edge [face of Pad26 from Sketch41.L17 | face of Pad26 from Sketch41.L10]; edge [face of Pad26 from Sketch41.L16 | face of Pad26 from Sketch41.L17]; edge [face of Pad26 from Sketch41.L14 | face of Pad26 from Sketch41.L15]; edge [face of Pad26 from Sketch41.L13 | face of Pad26 from Sketch41.L14]; edge [face of Pad26 from Sketch41.L4 | face of Pad26 from Sketch41.L5]; edge [face of Pad26 from Sketch41.L3 | face of Pad26 from Sketch41.L4]; edge [face of Pad26 from Sketch41.L1 | face of Pad26 from Sketch41.L2]; edge [face of Pad26 from Sketch41.L8 | face of Pad26 from Sketch41.L1]; edge [face of Pad26 from Sketch41.L7 | face of Pad26 from Sketch41.L8]; edge [face of Pad26 from Sketch41.L6 | face of Pad26 from Sketch41.L7]
  Fillet20: radius 0.5, on edge [end face of Pocket8 | face of Pad26 from Sketch41.L6]; edge [end face of Pocket8 | face of Fillet19] (x11); edge [end face of Pocket8 | face of Pad26 from Sketch41.L8]; edge [end face of Pocket8 | face of Pad26 from Sketch41.L7]; edge [end face of Pocket8 | face of Pad26 from Sketch41.L1]; edge [end face of Pocket8 | face of Pad26 from Sketch41.L2]; edge [end face of Pocket8 | face of Pad26 from Sketch41.L3]; edge [end face of Pocket8 | face of Pad26 from Sketch41.L4]; edge [end face of Pocket8 | face of Pad26 from Sketch41.L5]; edge [end face of Pocket8 | face of Pad26 from Sketch41.L15]; edge [end face of Pocket8 | face of Pad26 from Sketch41.L14]; edge [end face of Pocket8 | face of Pad26 from Sketch41.L13]; edge [end face of Pocket8 | face of Pad26 from Sketch41.L11]; edge [end face of Pocket8 | face of Pad26 from Sketch41.L10]; edge [end face of Pocket8 | face of Pad26 from Sketch41.L17]; edge [end face of Pocket8 | face of Pad26 from Sketch41.L16]
  Plane3: type Angle, RefPlane zx-plane, Direction X axis, Angle 135
  Sketch57 on Plane3, origin (0, 0, 0), H (1, 0, 0), V (0, 0.7071, 0.7071)
    point P1 (0, 43.1909)
    line L1 (0, 43.1909) -> (-3.9067, 44.8115)
    line L2 (-3.9067, 44.8115) -> (-8.3131, 34.1892)
    line L3 (-8.3131, 34.1892) -> (0, 30.7407)
    point P4 (0, 30.7407)
    line L4 (0, 30.7407) -> (0, 43.1909)
    reference projected point E1 (0, 62.7407) from vertex [face of Pad10 from Sketch17.A5 | face of Pad10 from Sketch17.A6 | face of Pad9]
    distance P4 E1 = 32
    length L2 = 11.5
    length L3 = 9
    length L1 = 4.2295
    coincidence: P1 V, P4 V
    perpendicularity: L2 L1
    parallelism: L3 L1
    vertical: L4 V
  Point1: type OnSurface, Support end face of Pocket8, RefPoint vertex [element of Sketch57 | element of Sketch57], Length 3, Direction (0, 0.6832, 0.7303)
  Line1: type PtDir, RefPoint Point1, Direction Sketch57.L1, Start 0, End 20
  Shaft1: profile Sketch57, axis Line1, angle 360
  Plane4: type Offset, RefPlane face of Shaft1 from Sketch57.L2, Offset 9
  Sketch58 on Plane4, origin (-10.8798, 3.1913, 3.1913), H (0.2815, 0.9596, 0), V (0.26, -0.0763, 0.9626)
    projected arc E1 centre (31.0473, 28.8138) radius 13.9633 from (30.6153, 14.8572) to (17.1003, 29.4888) ccw from edge [face of Shaft1 from Sketch57.L4 | face of Shaft1 from Sketch57.L3]
    projected arc E2 centre (31.0473, 28.8138) radius 13.9633 from (24.7133, 41.2579) to (42.1049, 20.2872) ccw from edge [face of Shaft1 from Sketch57.L3 | face of Shaft1 from Sketch57.L2]
    projected arc E3 centre (31.0473, 28.8138) radius 13.9633 from (17.1003, 29.4888) to (30.6153, 14.8572) ccw from edge [face of Shaft1 from Sketch57.L3 | face of Shaft1 from Sketch57.L2]
    offset arc E4 centre (31.0473, 28.8138) radius 12.9633 from (30.6462, 15.8567) to (18.0991, 29.4405) ccw from edge [face of Shaft1 from Sketch57.L4 | face of Shaft1 from Sketch57.L3]
    offset arc E5 centre (31.0473, 28.8138) radius 12.9633 from (30.6462, 15.8567) to (25.1669, 40.3667) ccw from edge [face of Shaft1 from Sketch57.L4 | face of Shaft1 from Sketch57.L3]
    point P5 (30.6462, 15.8567)
    offset arc E6 centre (31.0473, 28.8138) radius 12.9633 from (25.1669, 40.3667) to (41.313, 20.8978) ccw from edge [face of Shaft1 from Sketch57.L3 | face of Shaft1 from Sketch57.L2]
    offset arc E7 centre (31.0473, 28.8138) radius 12.9633 from (25.1669, 40.3667) to (30.6462, 15.8567) ccw from edge [face of Shaft1 from Sketch57.L3 | face of Shaft1 from Sketch57.L2]
    point P9 (30.6462, 15.8567)
    coincidence: E6 P9, P9 P5
  Sketch59 on zx-plane, origin (0, 0, 0), H (-1, 0, 0), V (0, 0, 1)
    line L1 (-1.6, 49.0243) -> (-11.6, 49.0243)
    line L2 (-11.6, 49.0243) -> (-11.6, 12.5644)
    line L3 (-11.6, 12.5644) -> (-1.6, 12.5644)
    line L4 (-1.6, 12.5644) -> (-1.6, 49.0243)
    reference projected line E1 (-1.6, -62.4295) -> (-1.6, 71.425) from edge [face of Pad1 from Sketch1.A1 | face of Pad9]
    reference projected line E2 (0, 65.6137) -> (3.8, 65.6137) from edge [face of Pad10 from Sketch17.L8 | face of Pad10 from Sketch17.A22]
    distance L4 E1 = 0
    length L1 = 10
    distance L1 E2 = 16.5893
    length L2 = 36.46
    horizontal: L1 H, L3 H
    vertical: L2 V, L4 V
  Pocket13: profile Sketch59, direction (0, 1, 0), through (limit type 6)
  Pocket14: profile Sketch58, direction (-0.9237, 0.2709, 0.2709), length 8.5
  Pocket15: profile Sketch58, direction (0.9237, -0.2709, -0.2709), length 8.5
  Sketch60 on face of Shaft1 from Sketch57.L2, origin (-19.1929, 5.6297, 5.6297), H (-0.2815, -0.9596, 0), V (0.26, -0.0763, 0.9626)
    circle A1 centre (-31.0473, 28.8138) radius 4.15
    projected circle E1 centre (-31.0473, 28.8138) radius 2.465 from edge [face of Shaft1 from Sketch57.L2 | face of Shaft1 from Sketch57.L1]
    radius A1 = 4.15
    concentricity: A1 E1
  Pad28: profile Sketch60, direction (-0.9237, 0.2709, 0.2709), length 1.9
  Sketch61 on end face of Pocket14, origin (-18.7311, 5.4943, 5.4943), H (0.2815, 0.9596, 0), V (0.26, -0.0763, 0.9626)
    circle A1 centre (31.0473, 28.8138) radius 5.75
    reference projected circle E1 centre (31.0473, 28.8138) radius 2.465 from edge [end face of Pocket14 | face of Pad28]
    projected circle E2 centre (31.0473, 28.8138) radius 2.465 from edge [end face of Pocket14 | face of Pad28]
    radius A1 = 5.75
    concentricity: E1 A1
  Pad29: profile Sketch61, direction (0.9237, -0.2709, -0.2709), length 2.2
  Sketch62 on end face of Pad29, origin (-16.699, 4.8982, 4.8982), H (0.2815, 0.9596, 0), V (0.26, -0.0763, 0.9626)
    line L1 (29.0473, 35.8788) -> (33.0473, 35.8788)
    line L2 (33.0473, 35.8788) -> (34.5473, 37.3788)
    point P3 (34.5473, 37.3788)
    line L3 (34.5473, 37.3788) -> (27.5473, 37.3788)
    line L4 (27.5473, 37.3788) -> (29.0473, 35.8788)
